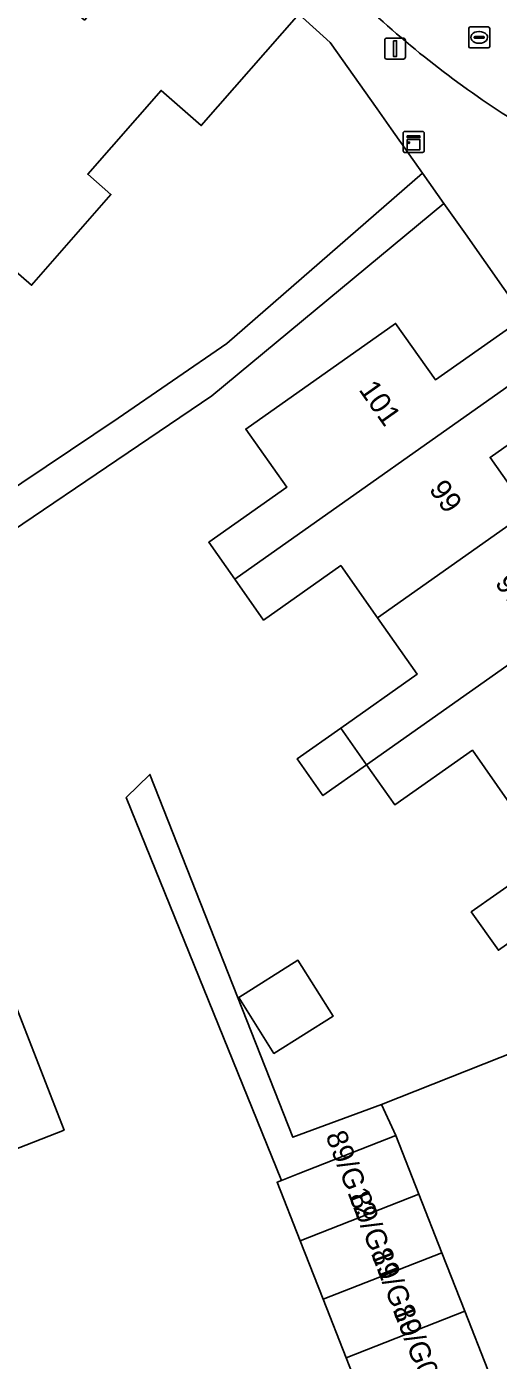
# Model space of a CAD drawing. Extents: x 158472 to 159562, y 388525 to 389606.
# Drawn here: x 159024.3 to 159046.8, y 388682.4 to 388745.9 of the extents above; entities that cross this region are included whole.
import ezdxf

# ---------------------------------------------------------------- set-up
doc = ezdxf.new("R2010")
doc.units = 0
for name, color, linetype in [('IMGEO_Erf', 7, 'Continuous'), ('IMGEO_Kast', 7, 'Continuous'), ('IMGEO_Lichtmast', 7, 'Continuous'), ('IMGEO_Pand', 7, 'Continuous'), ('IMGEO_Pand_nummerreeks', 7, 'Continuous'), ('IMGEO_Rijbaan_lokaal_open', 7, 'Continuous'), ('IMGEO_Rioolput', 7, 'Continuous'), ('IMGEO_Voetpad_onverhard', 7, 'Continuous'), ('IMGEO_Voetpad_open', 7, 'Continuous')]:
    doc.layers.add(name, color=color, linetype=linetype)

msp = doc.modelspace()

# ---------------------------------------------------------------- linework, layer by layer
at = {"layer": 'IMGEO_Erf'}
for points in [[(159037.306, 388746.524), (159033.754, 388750), (159022.695, 388760.564), (159020.525, 388760.662), (159011.339, 388750), (159010.514, 388749.043), (159009.78, 388749.669), (159008.795, 388748.524), (159000, 388738.293), (158998.201, 388736.2), (158995.302, 388732.827), (158995.915, 388732.321), (158995.466, 388731.797), (159000, 388727.495), (159000.69, 388728.273), (159011.112, 388719.033), (159004.481, 388711.554), (159004.663, 388711.139), (159028.696, 388727.272), (159033.871, 388730.833), (159043.209, 388738.936), (159041.709, 388741.062), (159041.036, 388742.015), (159038.809, 388745.171)], [(159024.448, 388748.546), (159027.089, 388746.235), (159030.384, 388750), (159031.558, 388751.342), (159033.092, 388750), (159034.32, 388748.925), (159034.425, 388749.045), (159037.306, 388746.524), (159032.658, 388741.213), (159030.744, 388742.887), (159027.25, 388738.894), (159028.355, 388737.927), (159024.568, 388733.599), (159023.453, 388734.575), (159016.379, 388726.491), (159010.325, 388731.789), (159009.336, 388730.659), (159005.044, 388734.415), (159006.048, 388735.562), (159001.992, 388739.111), (159007.562, 388745.475), (159015.603, 388738.438)], [(159050.655, 388728.379), (159046.422, 388725.393), (159048.237, 388722.82), (159050.065, 388720.228), (159054.231, 388723.167)], [(159018.486, 388688.756), (159013.828, 388686.936), (159013.29, 388688.314), (159008.268, 388686.351), (159005.198, 388694.206), (159015.17, 388698.104), (159010.285, 388710.604), (159018.101, 388713.659), (159020.053, 388708.665), (159021.417, 388709.199), (159023.237, 388704.542), (159023.505, 388703.856), (159022.209, 388703.349), (159026.12, 388693.342), (159018.588, 388690.398), (159019.131, 388689.008)], [(159034.442, 388699.659), (159037.267, 388701.434), (159038.944, 388698.764), (159036.12, 388696.989)]]:
    msp.add_lwpolyline(points, close=True, dxfattribs=at)
for points in [[(159047.356, 388708.925), (159045.58, 388711.443), (159041.887, 388708.838), (159040.538, 388710.751), (159038.456, 388709.282), (159037.223, 388711.03), (159039.305, 388712.499), (159042.953, 388715.072), (159041.06, 388717.755), (159039.308, 388720.239), (159035.632, 388717.646), (159034.259, 388719.593), (159033.018, 388721.353), (159036.734, 388723.974), (159034.778, 388726.747), (159041.923, 388731.786), (159043.825, 388729.088), (159048.052, 388732.069), (159045.246, 388736.047), (159044.219, 388737.503), (159033.169, 388728.335), (159005.095, 388709.33)], [(159040.658, 388679.695), (159039.563, 388682.484), (159038.467, 388685.274), (159037.372, 388688.063), (159036.276, 388690.852), (159036.491, 388690.936), (159029.082, 388709.192), (159030.208, 388710.286), (159037.025, 388692.999), (159041.242, 388694.55), (159056.691, 388700.672)], [(159046.82, 388701.91), (159045.531, 388703.737), (159049.194, 388706.32)]]:
    msp.add_lwpolyline(points, dxfattribs=at)
at = {"layer": 'IMGEO_Kast'}
for p, q in [((159042.285, 388740.005), (159042.285, 388740.846)), ((159042.285, 388740.846), (159042.285, 388740.005)), ((159042.36, 388740.93), (159043.201, 388740.93)), ((159043.201, 388740.93), (159042.36, 388740.93)), ((159043.285, 388740.855), (159043.285, 388740.014)), ((159043.285, 388740.014), (159043.285, 388740.855)), ((159043.21, 388739.93), (159042.369, 388739.93)), ((159042.369, 388739.93), (159043.21, 388739.93))]:
    msp.add_line(p, q, dxfattribs=at)
for points in [[(159042.48, 388740.72), (159043.08, 388740.72), (159043.08, 388740.635), (159042.48, 388740.635), (159042.48, 388740.72)], [(159042.48, 388740.545), (159043.08, 388740.545), (159043.08, 388740.056), (159042.48, 388740.056), (159042.48, 388740.545)]]:
    msp.add_lwpolyline(points, dxfattribs=at)
msp.add_circle((159042.564, 388740.394), 0.0377, dxfattribs=at)
for centre, start, end in [((159042.363, 388740.852), 92.4484, 184.28452), ((159042.363, 388740.852), 92.4484, 184.28452), ((159043.207, 388740.852), 2.4484, 94.28452), ((159043.207, 388740.852), 2.4484, 94.28452), ((159042.363, 388740.008), 182.4484, 274.28452), ((159042.363, 388740.008), 182.4484, 274.28452), ((159043.207, 388740.008), 272.4484, 4.28452), ((159043.207, 388740.008), 272.4484, 4.28452)]:
    msp.add_arc(centre, 0.0779, start, end, dxfattribs=at)
at = {"layer": 'IMGEO_Lichtmast'}
for p, q in [((159041.401, 388744.48), (159041.401, 388745.28)), ((159041.401, 388745.28), (159041.401, 388744.48)), ((159041.501, 388745.38), (159042.291, 388745.38)), ((159042.291, 388745.38), (159041.501, 388745.38)), ((159042.391, 388745.28), (159042.391, 388744.48)), ((159042.391, 388744.48), (159042.391, 388745.28)), ((159042.291, 388744.38), (159041.501, 388744.38)), ((159041.501, 388744.38), (159042.291, 388744.38))]:
    msp.add_line(p, q, dxfattribs=at)
msp.add_lwpolyline([(159041.821, 388745.255), (159041.971, 388745.255), (159041.971, 388744.505), (159041.821, 388744.505), (159041.821, 388745.255)], dxfattribs=at)
for centre, start, end in [((159041.501, 388745.28), 90, 180), ((159041.501, 388745.28), 90, 180), ((159042.291, 388745.28), 0, 90), ((159042.291, 388745.28), 360, 90), ((159041.501, 388744.48), 180, 270), ((159041.501, 388744.48), 180, 270), ((159042.291, 388744.48), 270, 0), ((159042.291, 388744.48), 270, 0)]:
    msp.add_arc(centre, 0.1, start, end, dxfattribs=at)
at = {"layer": 'IMGEO_Pand'}
for points in [[(159037.306, 388746.524), (159034.425, 388749.045), (159034.32, 388748.925), (159033.092, 388750), (159031.558, 388751.342), (159030.384, 388750), (159027.089, 388746.235), (159024.448, 388748.546), (159015.603, 388738.438), (159007.562, 388745.475), (159001.992, 388739.111), (159006.048, 388735.562), (159005.044, 388734.415), (159009.336, 388730.659), (159010.325, 388731.789), (159016.379, 388726.491), (159023.453, 388734.575), (159024.568, 388733.599), (159028.355, 388737.927), (159027.25, 388738.894), (159030.744, 388742.887), (159032.658, 388741.213)], [(159034.259, 388719.593), (159049.344, 388730.238), (159048.052, 388732.069), (159043.825, 388729.088), (159041.923, 388731.786), (159034.778, 388726.747), (159036.734, 388723.974), (159033.018, 388721.353)], [(159048.237, 388722.82), (159046.422, 388725.393), (159050.655, 388728.379), (159049.344, 388730.238), (159034.259, 388719.593), (159035.632, 388717.646), (159039.308, 388720.239), (159041.06, 388717.755)], [(159048.237, 388722.82), (159041.06, 388717.755), (159042.953, 388715.072), (159039.305, 388712.499), (159040.538, 388710.751), (159055.528, 388721.328), (159054.231, 388723.167), (159050.065, 388720.228)], [(159047.356, 388708.925), (159054.484, 388713.955), (159052.654, 388716.549), (159056.824, 388719.491), (159055.528, 388721.328), (159040.538, 388710.751), (159041.887, 388708.838), (159045.58, 388711.443)], [(159047.356, 388708.925), (159049.194, 388706.32), (159045.531, 388703.737), (159046.82, 388701.91), (159061.816, 388712.493), (159060.493, 388714.369), (159056.285, 388711.401), (159054.484, 388713.955)], [(159018.486, 388688.756), (159019.131, 388689.008), (159018.588, 388690.398), (159026.12, 388693.342), (159022.209, 388703.349), (159023.505, 388703.856), (159023.237, 388704.542), (159021.417, 388709.199), (159020.053, 388708.665), (159018.101, 388713.659), (159010.285, 388710.604), (159015.17, 388698.104), (159005.198, 388694.206), (159008.268, 388686.351), (159013.29, 388688.314), (159013.828, 388686.936)], [(159039.305, 388712.499), (159037.223, 388711.03), (159038.456, 388709.282), (159040.538, 388710.751)], [(159034.442, 388699.659), (159036.12, 388696.989), (159038.944, 388698.764), (159037.267, 388701.434)], [(159041.934, 388693.074), (159037.281, 388691.247), (159036.491, 388690.936), (159036.276, 388690.852), (159037.372, 388688.063), (159043.03, 388690.285)], [(159037.372, 388688.063), (159038.467, 388685.274), (159044.125, 388687.496), (159043.03, 388690.285)], [(159039.563, 388682.484), (159045.22, 388684.707), (159044.125, 388687.496), (159038.467, 388685.274)], [(159039.563, 388682.484), (159040.658, 388679.695), (159046.316, 388681.918), (159045.22, 388684.707)]]:
    msp.add_lwpolyline(points, close=True, dxfattribs=at)
at = {"layer": 'IMGEO_Rijbaan_lokaal_open'}
msp.add_lwpolyline([(159053.954, 388681.666), (159053.067, 388683.904), (159052.136, 388686.253), (159049.847, 388692.152), (159049.044, 388694.177), (159053.938, 388696.117), (159057.922, 388697.827), (159067.53, 388704.236), (159065.814, 388706.73), (159056.691, 388700.672), (159041.242, 388694.55), (159041.934, 388693.074), (159043.03, 388690.285), (159044.125, 388687.496), (159045.22, 388684.707), (159046.316, 388681.918)], dxfattribs=at)
msp.add_arc((159072.299, 388780.718), 46.41, 226.01221, 237.32728, dxfattribs=at)
at = {"layer": 'IMGEO_Rioolput'}
for p, q in [((159045.405, 388744.986), (159045.405, 388745.838)), ((159045.48, 388745.912), (159046.332, 388745.912)), ((159045.893, 388745.692), (159045.918, 388745.692)), ((159046.406, 388745.838), (159046.406, 388744.986)), ((159046.332, 388744.912), (159045.48, 388744.912)), ((159045.664, 388745.406), (159045.664, 388745.418)), ((159046.102, 388745.369), (159045.704, 388745.369)), ((159045.707, 388745.455), (159046.105, 388745.455)), ((159045.916, 388745.132), (159045.891, 388745.132)), ((159046.148, 388745.418), (159046.148, 388745.406))]:
    msp.add_line(p, q, dxfattribs=at)
for points in [[(159045.405, 388744.986), (159045.405, 388745.838)], [(159045.48, 388745.912), (159046.332, 388745.912)], [(159046.406, 388745.838), (159046.406, 388744.986)], [(159046.332, 388744.912), (159045.48, 388744.912)]]:
    msp.add_lwpolyline(points, dxfattribs=at)
for centre, radius, start, end in [((159045.482, 388745.836), 0.0765, 91.55205, 178.44795), ((159045.482, 388745.836), 0.0765, 91.55205, 178.44795), ((159046.33, 388745.836), 0.0765, 1.55205, 88.44795), ((159046.33, 388745.836), 0.0765, 1.55205, 88.44795), ((159045.482, 388744.988), 0.0765, 181.55205, 268.44795), ((159045.482, 388744.988), 0.0765, 181.55205, 268.44795), ((159045.704, 388745.415), 0.0403, 85.87752, 175.75265), ((159045.701, 388745.405), 0.0366, 178.93798, 274.71019), ((159046.105, 388745.412), 0.043, 264.86636, 352.45326), ((159046.109, 388745.417), 0.0386, 1.73085, 96.63898), ((159046.33, 388744.988), 0.0765, 271.55205, 358.44795), ((159046.33, 388744.988), 0.0765, 271.55205, 358.44795)]:
    msp.add_arc(centre, radius, start, end, dxfattribs=at)
for centre, major_axis, ratio, start_param, end_param in [((159045.892, 388745.412), (-0.387, 0.002), 0.722429, 4.712389, 7.853982), ((159045.917, 388745.412), (-0.39, 0.002), 0.717154, 1.570796, 4.712389)]:
    msp.add_ellipse(centre, major_axis=major_axis, ratio=ratio, start_param=start_param, end_param=end_param, dxfattribs=at)
at = {"layer": 'IMGEO_Voetpad_onverhard'}
msp.add_lwpolyline([(159033.169, 388728.335), (159044.219, 388737.503), (159043.209, 388738.936), (159033.871, 388730.833), (159028.696, 388727.272), (159004.663, 388711.139), (159005.214, 388709.882), (159005.095, 388709.33)], close=True, dxfattribs=at)
at = {"layer": 'IMGEO_Voetpad_open'}
msp.add_lwpolyline([(159037.306, 388746.524), (159038.809, 388745.171), (159041.036, 388742.015), (159041.709, 388741.062), (159043.209, 388738.936), (159044.219, 388737.503), (159045.246, 388736.047), (159048.052, 388732.069), (159049.344, 388730.238), (159050.655, 388728.379), (159054.231, 388723.167), (159055.528, 388721.328), (159056.824, 388719.491), (159059.095, 388720.765), (159050.19, 388733.485), (159053.593, 388735.868)], dxfattribs=at)
msp.add_lwpolyline([(159029.082, 388709.192), (159036.491, 388690.936), (159037.281, 388691.247), (159041.934, 388693.074), (159041.242, 388694.55), (159037.025, 388692.999), (159030.208, 388710.286)], close=True, dxfattribs=at)
msp.add_arc((159072.299, 388780.718), 46.41, 226.01221, 237.32728, dxfattribs=at)

# ---------------------------------------------------------------- texts
at = {"layer": 'IMGEO_Pand_nummerreeks'}
for s, rotation, p in [('101', 305.14325, (159040.138, 388728.624)), ('99', 305.14325, (159043.482, 388723.873)), ('97', 305.14325, (159046.627, 388719.406)), ('89/G12', 291.11901, (159038.571, 388693.077)), ('89/G11', 291.12119, (159039.689, 388690.182)), ('89/G10', 291.12119, (159040.727, 388687.495)), ('89/G09', 291.12119, (159041.768, 388684.8))]:
    msp.add_text(s, height=1, rotation=rotation, dxfattribs=at).set_placement(p)

doc.saveas('drawing.dxf')
